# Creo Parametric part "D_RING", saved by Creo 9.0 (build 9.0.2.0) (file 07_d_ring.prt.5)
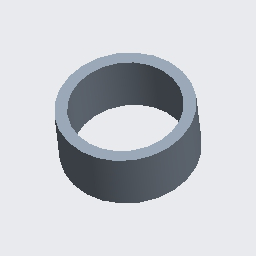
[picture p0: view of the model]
Units: millimeter Newton Second (mmNs); MM, TONNE, SECS

Created from: XX_MMNS_PART_SOLID_ABS.PRT

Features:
  1. datum plane "RIGHT"
  2. datum plane "TOP"
  3. datum plane "FRONT"
  4. coordinate system
  5. extrusion "Extrude 1"

Surfaces: 2 plane, 2 cylinder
